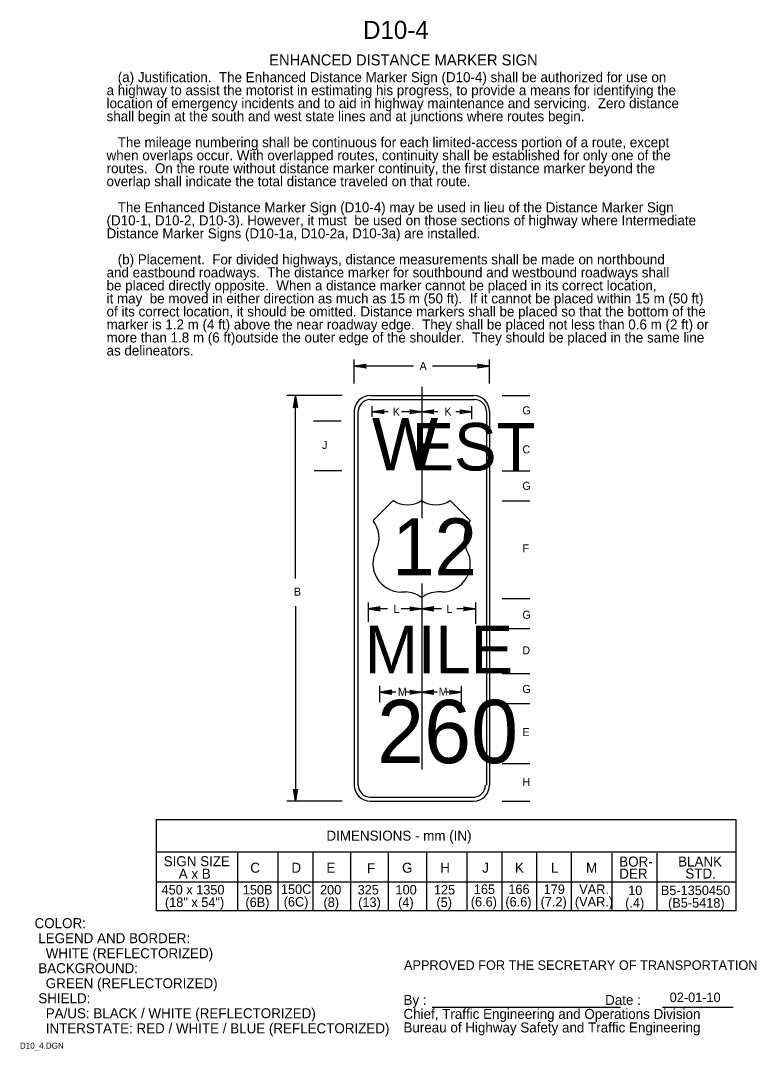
# Model space of a CAD drawing. Extents: x 0.013 to 0.196, y 0.006 to 0.263.
import ezdxf

# ---------------------------------------------------------------- set-up
doc = ezdxf.new("R2010")
doc.units = 0
for name, color, linetype in [('1', 7, 'Continuous'), ('2', 7, 'Continuous'), ('3', 7, 'Continuous'), ('4', 7, 'Continuous')]:
    doc.layers.add(name, color=color, linetype=linetype)

# ---------------------------------------------------------------- blocks, each defined once
blk = doc.blocks.new('RARROW')
at = {"layer": '3'}
for p, q in [((-2.156, 0.28500000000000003), (-2.2665, 0.384625)), ((-2.2665, 0.384625), (0, 0)), ((0, 0), (-2.2665, -0.379125)), ((-2.156, 0.28500000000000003), (-2.075625, 0.12075)), ((0, 0), (-2.156, 0.28500000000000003)), ((-2.14975, -0.2705), (0, 0)), ((-2.075625, 0.12075), (0, 0)), ((0, 0), (-2.074, -0.108)), ((-2.2665, -0.379125), (-2.14975, -0.2705)), ((-2.074, -0.108), (-2.14975, -0.2705))]:
    blk.add_line(p, q, dxfattribs=at)

msp = doc.modelspace()

# ---------------------------------------------------------------- linework, layer by layer
at = {"layer": '1'}
for p, q in [((0.11543984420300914, 0.01694517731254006), (0.1624214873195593, 0.01694517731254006)), ((0.17295324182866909, 0.01694517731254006), (0.19056484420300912, 0.01694517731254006))]:
    msp.add_line(p, q, dxfattribs=at)
at = {"layer": '2'}
for p, q in [((0.10569938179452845, 0.1434720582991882), (0.10068942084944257, 0.13841249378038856)), ((0.11988600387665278, 0.1434720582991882), (0.12489596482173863, 0.13841249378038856)), ((0.12405270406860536, 0.1310711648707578), (0.12405270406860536, 0.1310711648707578)), ((0.10773312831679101, 0.12060481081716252), (0.10872519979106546, 0.12060481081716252)), ((0.11785225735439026, 0.12060481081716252), (0.11681058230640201, 0.12060481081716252))]:
    msp.add_line(p, q, dxfattribs=at)
for centre, radius, start, end in [((0.10923202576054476, 0.14853701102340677), 0.00618205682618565, 235.00798055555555, 304.9920222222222), ((0.11632237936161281, 0.14853701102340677), 0.006182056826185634, 235.0079777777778, 304.99201944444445), ((0.09506926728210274, 0.13406553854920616), 0.007090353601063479, 335.7034111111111, 38.02486944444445), ((0.1304661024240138, 0.13405831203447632), 0.0070700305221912, 141.9852277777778, 204.30668333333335), ((0.1077126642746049, 0.12767428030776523), 0.0070903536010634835, 150.66324166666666, 270), ((0.11785310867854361, 0.12768164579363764), 0.007076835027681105, 269.99310833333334, 29.329866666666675), ((0.10868022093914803, 0.11406422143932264), 0.006540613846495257, 51.21564444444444, 89.87545277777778), ((0.11684947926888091, 0.11413460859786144), 0.00647031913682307, 90.34444166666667, 129.00425)]:
    msp.add_arc(centre, radius, start, end, dxfattribs=at)
at = {"layer": '3'}
for p, q in [((0.09596843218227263, 0.1726680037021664), (0.09596843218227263, 0.17862374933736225)), ((0.12971843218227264, 0.1726680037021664), (0.12971843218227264, 0.17862374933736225)), ((0.11073762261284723, 0.17700783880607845), (0.09596843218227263, 0.17700783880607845)), ((0.12971843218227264, 0.17700783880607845), (0.11546922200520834, 0.17700783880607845)), ((0.11284343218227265, 0.1718454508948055), (0.1128434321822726, 0.13903403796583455)), ((0.09294186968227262, 0.16964144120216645), (0.0791107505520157, 0.16964144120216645)), ((0.08127743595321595, 0.12400072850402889), (0.08127743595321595, 0.16964144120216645)), ((0.09996843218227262, 0.16964144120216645), (0.12571843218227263, 0.1696414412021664)), ((0.09996843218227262, 0.16864144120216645), (0.1259684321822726, 0.1686414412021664)), ((0.13290942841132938, 0.16964144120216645), (0.13978442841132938, 0.16964144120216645)), ((0.09596843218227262, 0.16564144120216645), (0.09596843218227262, 0.07239144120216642)), ((0.09696843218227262, 0.07239144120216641), (0.09696843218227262, 0.16564144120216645)), ((0.10039343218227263, 0.16430916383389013), (0.10039343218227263, 0.16697651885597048)), ((0.10444878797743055, 0.1656037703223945), (0.10039343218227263, 0.1656037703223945)), ((0.11284343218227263, 0.1656037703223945), (0.107742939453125, 0.1656037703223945)), ((0.11678688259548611, 0.1656037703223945), (0.11284343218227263, 0.1656037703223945)), ((0.12529343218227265, 0.1656037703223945), (0.12127890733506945, 0.1656037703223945)), ((0.12529343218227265, 0.1637305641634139), (0.12529343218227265, 0.16697651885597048)), ((0.12896843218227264, 0.16564144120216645), (0.12896843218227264, 0.0723914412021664)), ((0.12971843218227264, 0.16564144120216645), (0.12971843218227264, 0.0723914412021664)), ((0.09269847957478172, 0.16326644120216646), (0.08582347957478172, 0.16326644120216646)), ((0.13290942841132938, 0.16214144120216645), (0.13978442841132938, 0.16214144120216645)), ((0.09281826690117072, 0.15089144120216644), (0.08594326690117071, 0.15089144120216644)), ((0.13290942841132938, 0.15089144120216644), (0.13978442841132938, 0.15089144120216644)), ((0.13290942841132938, 0.14339144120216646), (0.13978442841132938, 0.14339144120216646)), ((0.1128434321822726, 0.12274296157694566), (0.11284343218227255, 0.07628072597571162)), ((0.13290942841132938, 0.11901644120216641), (0.13978442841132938, 0.11901644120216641)), ((0.08127743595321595, 0.11705306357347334), (0.08127743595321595, 0.06839144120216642)), ((0.09941843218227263, 0.11801136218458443), (0.09941843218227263, 0.11312794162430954)), ((0.1042691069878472, 0.11639545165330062), (0.09941843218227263, 0.11639545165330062)), ((0.1128434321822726, 0.11639545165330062), (0.10768304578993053, 0.11639545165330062)), ((0.1177451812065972, 0.11639545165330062), (0.11284343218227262, 0.11639545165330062)), ((0.1262684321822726, 0.11639545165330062), (0.12157837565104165, 0.11639545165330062)), ((0.12626843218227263, 0.11801136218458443), (0.12626843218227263, 0.11264879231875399)), ((0.13290942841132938, 0.1115164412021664), (0.13978442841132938, 0.1115164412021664)), ((0.13290942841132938, 0.1002664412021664), (0.13978442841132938, 0.1002664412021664)), ((0.10238245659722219, 0.0930560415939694), (0.10238245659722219, 0.09716836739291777)), ((0.10636538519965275, 0.09555245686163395), (0.10238245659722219, 0.09555245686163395)), ((0.11284343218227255, 0.09555245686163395), (0.10864134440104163, 0.09555245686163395)), ((0.11666709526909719, 0.09555245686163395), (0.11284343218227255, 0.09555245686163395)), ((0.12274630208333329, 0.09555245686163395), (0.11870347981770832, 0.09555245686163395)), ((0.12274630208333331, 0.09257689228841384), (0.12274630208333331, 0.09716836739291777)), ((0.13290942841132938, 0.09276644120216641), (0.13978442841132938, 0.09276644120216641)), ((0.13290942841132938, 0.0777664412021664), (0.13978442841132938, 0.0777664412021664)), ((0.09294186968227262, 0.06839144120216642), (0.0791107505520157, 0.06839144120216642)), ((0.09996843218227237, 0.06939144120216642), (0.12598055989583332, 0.0693914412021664)), ((0.09996843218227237, 0.06839144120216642), (0.1257184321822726, 0.06839144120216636)), ((0.13290942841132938, 0.06839144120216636), (0.13978442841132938, 0.06839144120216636)), ((0.04650229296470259, 0.06378743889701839), (0.19123038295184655, 0.06378743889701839)), ((0.04650229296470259, 0.06378743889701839), (0.04650229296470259, 0.04096243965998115)), ((0.19123038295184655, 0.06378743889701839), (0.19123038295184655, 0.04096243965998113)), ((0.19123038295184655, 0.055662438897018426), (0.04650229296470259, 0.055662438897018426)), ((0.06679665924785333, 0.05551146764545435), (0.06679665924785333, 0.04096243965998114)), ((0.07690543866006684, 0.055662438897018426), (0.07690543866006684, 0.04096243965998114)), ((0.08559666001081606, 0.05551146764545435), (0.08559666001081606, 0.04096243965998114)), ((0.09499665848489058, 0.05551146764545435), (0.09499665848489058, 0.04096243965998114)), ((0.1043966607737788, 0.05551146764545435), (0.1043966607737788, 0.04096243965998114)), ((0.11396651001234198, 0.0556624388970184), (0.11396651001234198, 0.04096243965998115)), ((0.12407528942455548, 0.055662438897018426), (0.12407528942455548, 0.04096243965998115)), ((0.1327665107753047, 0.05551146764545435), (0.1327665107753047, 0.04096243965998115)), ((0.14145773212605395, 0.055662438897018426), (0.14145773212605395, 0.04096243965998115)), ((0.15014895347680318, 0.05551146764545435), (0.15014895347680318, 0.04096243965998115)), ((0.16025772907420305, 0.055360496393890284), (0.16025772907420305, 0.04096243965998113)), ((0.17153773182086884, 0.055360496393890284), (0.17153773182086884, 0.04096243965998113)), ((0.04650229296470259, 0.04825393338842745), (0.19123038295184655, 0.04825393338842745)), ((0.19123038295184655, 0.04096243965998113), (0.04650229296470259, 0.04096243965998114))]:
    msp.add_line(p, q, dxfattribs=at)
for centre, radius, start, end in [((0.09996843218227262, 0.16564144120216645), 0.004, 90, 180), ((0.09996843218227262, 0.16564144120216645), 0.003, 90, 180), ((0.12571843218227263, 0.16564144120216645), 0.004, 0, 90), ((0.12596843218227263, 0.16564144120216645), 0.003, 0, 90), ((0.09996843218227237, 0.07239144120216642), 0.004, 180, 270), ((0.09996843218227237, 0.07239144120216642), 0.003, 180, 270), ((0.12571843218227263, 0.07239144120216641), 0.003, 270, 0), ((0.12571843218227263, 0.07239144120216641), 0.004, 270, 0)]:
    msp.add_arc(centre, radius, start, end, dxfattribs=at)

# ---------------------------------------------------------------- block references
at = {"layer": '3', "xscale": 0.0013236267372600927}
for p, yscale, rotation in [((0.09596843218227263, 0.17700783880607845), 0.001309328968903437, 180), ((0.08127743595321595, 0.16956013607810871), 0.001309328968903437, 90), ((0.10039343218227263, 0.1656037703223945), 0.001309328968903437, 180), ((0.11284343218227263, 0.1656037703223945), 0.001309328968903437, 180), ((0.09941843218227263, 0.11639545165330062), -0.001309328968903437, 180), ((0.11284343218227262, 0.11639545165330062), -0.001309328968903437, 180), ((0.10238245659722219, 0.09555245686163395), -0.001309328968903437, 180), ((0.11284343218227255, 0.09555245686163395), -0.001309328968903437, 180), ((0.08127743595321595, 0.06839144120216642), 0.001309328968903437, -90)]:
    msp.add_blockref('RARROW', p, dxfattribs=dict(at, yscale=yscale, rotation=rotation))
at = {"layer": '3', "xscale": 0.0013236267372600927, "yscale": 0.001309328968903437}
for p in [(0.12971843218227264, 0.17700783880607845), (0.11284343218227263, 0.1656037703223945), (0.12529343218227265, 0.1656037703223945), (0.1128434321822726, 0.11639545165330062), (0.1262684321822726, 0.11639545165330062), (0.11284343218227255, 0.09555245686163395), (0.12274630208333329, 0.09555245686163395)]:
    msp.add_blockref('RARROW', p, dxfattribs=at)

# ---------------------------------------------------------------- texts
at = {"layer": '1'}
for s, height, p in [('D10-4', 0.0045000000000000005, (0.09815774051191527, 0.2587015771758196)), ('ENHANCED DISTANCE MARKER SIGN', 0.00275025, (0.07472831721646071, 0.25207657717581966)), ('COLOR: ', 0.0024997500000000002, (0.01615434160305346, 0.03666212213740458)), (' LEGEND AND BORDER:', 0.0024997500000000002, (0.01615434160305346, 0.03291237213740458)), ('   WHITE (REFLECTORIZED)', 0.0024997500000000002, (0.01615434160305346, 0.02916262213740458)), ('APPROVED FOR THE SECRETARY OF TRANSPORTATION', 0.0023752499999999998, (0.108375, 0.02625)), (' BACKGROUND:', 0.0024997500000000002, (0.01615434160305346, 0.025412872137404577)), ('   GREEN (REFLECTORIZED)', 0.0024997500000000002, (0.01615434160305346, 0.021663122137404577)), (' SHIELD: ', 0.0024997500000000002, (0.01615434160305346, 0.01791337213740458)), ('By :                                                Date :', 0.0024997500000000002, (0.10825, 0.0175)), ('   PA/US: BLACK / WHITE (REFLECTORIZED)', 0.0024997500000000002, (0.01615434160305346, 0.01416362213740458)), ('Chief, Traffic Engineering and Operations Division', 0.0024997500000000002, (0.10825, 0.014)), ('   INTERSTATE: RED / WHITE / BLUE (REFLECTORIZED)', 0.0024997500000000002, (0.01615434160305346, 0.010413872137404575)), ('Bureau of Highway Safety and Traffic Engineering', 0.0024997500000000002, (0.10825, 0.010625)), ('D10_4.DGN', 0.0015, (0.0125, 0.006574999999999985))]:
    msp.add_text(s, height=height, dxfattribs=at).set_placement(p)
at = {"layer": '2'}
for s, p in [('   (a) Justification.  The Enhanced Distance Marker Sign (D10-4) shall be authorized for use on ', (0.034127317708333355, 0.24789421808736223)), ('a highway to assist the motorist in estimating his progress, to provide a means for identifying the', (0.034127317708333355, 0.2446444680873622)), ('location of emergency incidents and to aid in highway maintenance and servicing.  Zero distance', (0.034127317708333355, 0.2413947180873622)), ('shall begin at the south and west state lines and at junctions where routes begin.', (0.034127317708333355, 0.2381449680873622)), ('   The mileage numbering shall be continuous for each limited-access portion of a route, except', (0.034127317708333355, 0.2316454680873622)), ('when overlaps occur. With overlapped routes, continuity shall be established for only one of the', (0.034127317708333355, 0.2283957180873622)), ('routes.  On the route without distance marker continuity, the first distance marker beyond the', (0.034127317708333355, 0.22514596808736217)), ('overlap shall indicate the total distance traveled on that route.', (0.034127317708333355, 0.22189621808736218)), ('   The Enhanced Distance Marker Sign (D10-4) may be used in lieu of the Distance Marker Sign', (0.034127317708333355, 0.21539671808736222)), ('(D10-1, D10-2, D10-3). However, it must  be used on those sections of highway where Intermediate', (0.034127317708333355, 0.21214696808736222)), ('Distance Marker Signs (D10-1a, D10-2a, D10-3a) are installed.', (0.034127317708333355, 0.2088972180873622)), ('   (b) Placement.  For divided highways, distance measurements shall be made on northbound', (0.034127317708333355, 0.2023977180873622)), ('and eastbound roadways.  The distance marker for southbound and westbound roadways shall', (0.034127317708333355, 0.19914796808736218)), ('be placed directly opposite.  When a distance marker cannot be placed in its correct location,', (0.034127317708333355, 0.19589821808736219)), ('it may  be moved in either direction as much as 15 m (50 ft).  If it cannot be placed within 15 m (50 ft)', (0.034127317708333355, 0.1926484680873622)), ('of its correct location, it should be omitted. Distance markers shall be placed so that the bottom of the', (0.034127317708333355, 0.18939871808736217)), ('marker is 1.2 m (4 ft) above the near roadway edge.  They shall be placed not less than 0.6 m (2 ft) or', (0.034127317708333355, 0.18614896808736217)), ('more than 1.8 m (6 ft)outside the outer edge of the shoulder.  They should be placed in the same line', (0.034127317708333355, 0.18289921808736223)), ('as delineators. ', (0.034127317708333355, 0.1796494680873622))]:
    msp.add_text(s, height=0.0024997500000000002, dxfattribs=at).set_placement(p)
at = {"layer": '3'}
for s, height, p in [('A', 0.00200025, (0.11226305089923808, 0.17603832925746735)), ('K', 0.00200025, (0.10557964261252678, 0.16458759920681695)), ('K', 0.00200025, (0.11844104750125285, 0.16464749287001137)), ('G', 0.00200025, (0.13792649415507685, 0.16494696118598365)), ('J', 0.00200025, (0.08792405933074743, 0.15631491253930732)), ('C', 0.00200025, (0.13792649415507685, 0.1552116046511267)), ('G', 0.00200025, (0.13792649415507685, 0.1460987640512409)), ('F', 0.00200025, (0.13797374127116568, 0.1304912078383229)), ('B', 0.00200025, (0.0809046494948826, 0.11967967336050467)), ('L', 0.00200025, (0.10577805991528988, 0.11535500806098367)), ('L', 0.00200025, (0.11899538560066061, 0.11535500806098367)), ('G', 0.00200025, (0.13792649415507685, 0.11391756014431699)), ('MILE', 0.011863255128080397, (0.09859787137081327, 0.10032639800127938)), ('D', 0.00200025, (0.13792649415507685, 0.10503141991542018)), ('M', 0.00200025, (0.10685263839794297, 0.09467197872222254)), ('G', 0.00200025, (0.13792649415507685, 0.09539070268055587)), ('E', 0.00200025, (0.13793442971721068, 0.08460768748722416)), ('H', 0.00200025, (0.13798167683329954, 0.07215196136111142)), ('DIMENSIONS - mm (IN)', 0.0024997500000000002, (0.08902315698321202, 0.05850683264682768)), ('SIGN SIZE', 0.0024997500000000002, (0.04839613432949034, 0.05213183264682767)), ('BOR-', 0.0024997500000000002, (0.1621092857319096, 0.05203600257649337)), ('BLANK', 0.0024997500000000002, (0.17680918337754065, 0.052046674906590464)), ('A x B', 0.0024997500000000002, (0.05214613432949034, 0.04900683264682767)), ('C', 0.0024997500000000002, (0.07002113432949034, 0.05050683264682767)), ('D', 0.0024997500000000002, (0.08027113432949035, 0.05050683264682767)), ('E', 0.0024997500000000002, (0.08902113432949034, 0.05050683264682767)), ('F', 0.0024997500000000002, (0.09914613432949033, 0.05038183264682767)), ('G', 0.0024997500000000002, (0.10789613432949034, 0.05050683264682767)), ('H', 0.0024997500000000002, (0.11742242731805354, 0.050506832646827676)), ('J', 0.0024997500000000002, (0.12789586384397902, 0.050506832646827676)), ('K', 0.0024997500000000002, (0.13608342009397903, 0.050506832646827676)), ('L', 0.0024997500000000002, (0.14508082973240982, 0.050506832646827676)), ('M', 0.0024997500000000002, (0.15383184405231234, 0.050506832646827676)), ('DER', 0.0024997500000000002, (0.1621092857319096, 0.049036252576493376)), ('STD.', 0.0024997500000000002, (0.17860900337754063, 0.04904692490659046)), ('450 x 1350', 0.0023752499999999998, (0.0478488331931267, 0.04507277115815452)), ('150B', 0.0023752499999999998, (0.06813220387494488, 0.04507277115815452)), ('150C', 0.0023752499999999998, (0.07765523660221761, 0.04519777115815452)), ('200', 0.0023752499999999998, (0.08741675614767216, 0.04507277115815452)), ('325', 0.0023752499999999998, (0.09679967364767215, 0.04507277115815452)), ('100', 0.0023752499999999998, (0.10625768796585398, 0.04507277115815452)), ('125', 0.0023752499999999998, (0.11583545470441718, 0.04507277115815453)), ('165', 0.0023752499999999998, (0.12581045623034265, 0.04519777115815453)), ('166', 0.0023752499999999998, (0.1344343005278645, 0.04519777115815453)), ('179', 0.0023752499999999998, (0.14323760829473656, 0.04519777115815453)), ('VAR.', 0.0023752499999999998, (0.1521196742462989, 0.04519777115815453)), ('10', 0.0023752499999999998, (0.16435009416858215, 0.04492179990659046)), ('B5-1350450', 0.0023752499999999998, (0.1724929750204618, 0.04492179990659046)), ('(18" x 54")', 0.0023752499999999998, (0.04869924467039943, 0.041947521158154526)), ('(6B)', 0.0023752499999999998, (0.06878827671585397, 0.041947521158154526)), ('(6C)', 0.0023752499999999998, (0.0783458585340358, 0.042072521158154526)), ('(8)', 0.0023752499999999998, (0.0882851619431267, 0.041947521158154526)), ('(13)', 0.0023752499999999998, (0.09694038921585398, 0.041947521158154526)), ('(4)', 0.0023752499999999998, (0.10691016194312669, 0.041947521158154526)), ('(5)', 0.0023752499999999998, (0.1164800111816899, 0.04194752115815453)), ('(6.6)', 0.0023752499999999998, (0.12505145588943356, 0.04207252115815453)), ('(6.6)', 0.0023752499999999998, (0.13367817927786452, 0.04207252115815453)), ('(7.2)', 0.0023752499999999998, (0.1424778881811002, 0.04207252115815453)), ('(VAR.)', 0.0023752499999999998, (0.15103533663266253, 0.04207252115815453)), ('(.4)', 0.0023752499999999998, (0.16359901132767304, 0.04179654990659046)), ('(B5-5418)', 0.0023752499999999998, (0.17429708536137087, 0.04179654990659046))]:
    msp.add_text(s, height=height, dxfattribs=at).set_placement(p)
for s, height, p in [('W', 0.01310441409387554, (0.10037054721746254, 0.1509800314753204)), ('EST', 0.011863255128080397, (0.11031615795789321, 0.150936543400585)), ('12', 0.01421099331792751, (0.10544377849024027, 0.12478146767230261)), ('M', 0.00200025, (0.11704725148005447, 0.09473187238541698)), ('260', 0.01578999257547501, (0.10164856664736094, 0.07786500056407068))]:
    msp.add_text(s, height=height, rotation=360, dxfattribs=at).set_placement(p)
at = {"layer": '4'}
msp.add_text('02-01-10', height=0.0023752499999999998, dxfattribs=at).set_placement((0.17471512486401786, 0.018199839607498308))

doc.saveas('drawing.dxf')
